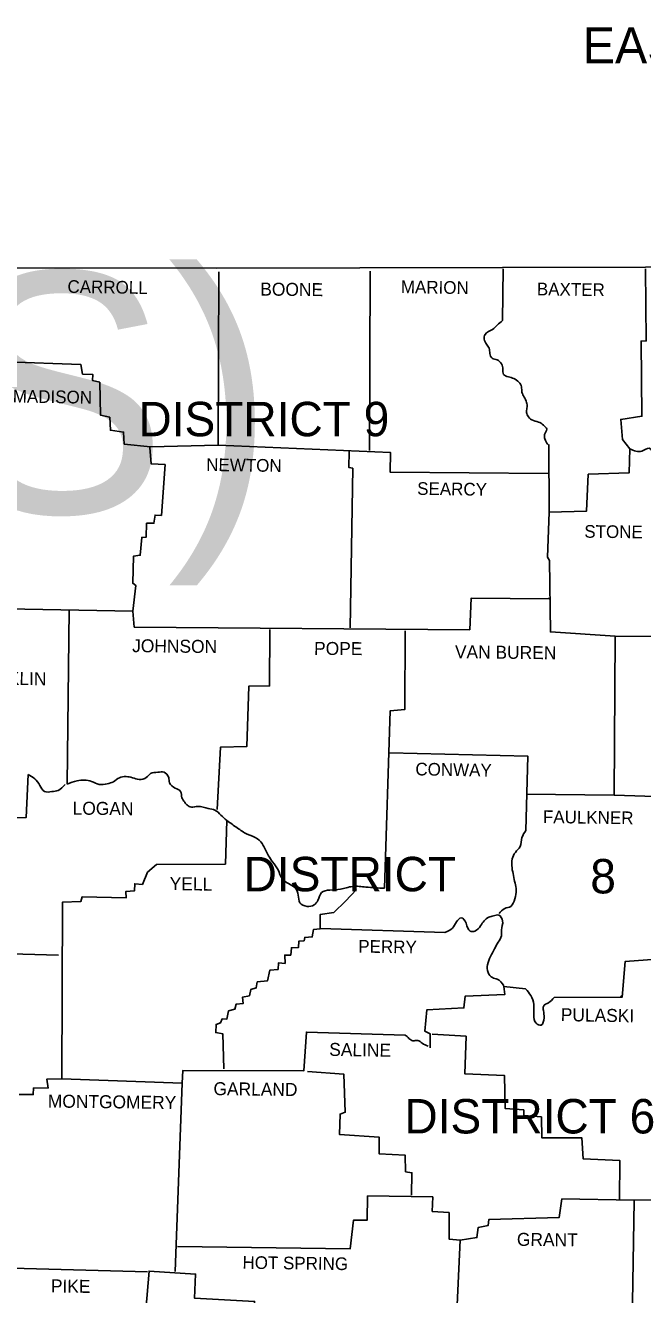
# Model space of a CAD drawing. Extents: x 152 to 3426, y 67 to 2142.
# Drawn here: x 2800 to 2999.8, y 1623.7 to 2035 of the extents above; entities that cross this region are included whole.
import ezdxf

# ---------------------------------------------------------------- set-up
doc = ezdxf.new("R2010")
doc.units = 0
for name, color, linetype in [('R_Border', 7, 'Continuous'), ('R_Grid', 7, 'Continuous'), ('S_AREA_CALC', 7, 'Continuous')]:
    doc.layers.add(name, color=color, linetype=linetype)

msp = doc.modelspace()

# ---------------------------------------------------------------- linework, layer by layer
at = {"layer": 'S_AREA_CALC'}
for points in [[(2703.71, 1956.42), (2861.92, 1956.32), (3000.75, 1956.61), (3164.54, 1959.16), (3240.46, 1960.92)], [(2793.82, 1925.89), (2817.89, 1925.11), (2818.47, 1921.98), (2821.8, 1921.88), (2821.7, 1919.92), (2824.05, 1919.34), (2824.25, 1908.67), (2827.28, 1907.99), (2827.48, 1903.78), (2831.78, 1903.19), (2831.98, 1899.28), (2840.49, 1898.4), (2862.4, 1898.89), (2862.6, 1955.15)], [(2911.62, 1955.34), (2911.33, 1897.22)], [(2954.67, 1956.03), (2954.47, 1939.3)], [(3000.75, 1956.03), (3000.95, 1932.74), (2999.28, 1932.64), (2999.58, 1908.28), (2992.73, 1907.3), (2993.32, 1900.75), (2995.66, 1897.71), (2995.47, 1889.98), (2982.16, 1889.5), (2981.67, 1877.56), (2969.54, 1877.17), (2968.95, 1862.69), (2969.64, 1861.51), (2969.93, 1838.42), (2990.87, 1837.05), (2990.58, 1785.49), (3007.21, 1785), (3007.21, 1732.56), (2994.1, 1731.58), (2993.12, 1720.04), (2971.11, 1719.94)], [(2711.44, 1897.22), (2729.73, 1897.13), (2730.22, 1903.58), (2736.97, 1903.58), (2737.56, 1914.05), (2775.72, 1912.68), (2776.89, 1915.62), (2792.64, 1915.72), (2784.72, 1893.02), (2783.15, 1856.72), (2781.98, 1856.62), (2781.39, 1845.66), (2787.17, 1845.17), (2788.05, 1846.05), (2834.72, 1845.17), (2835.21, 1839.99)], [(2840.29, 1898.2), (2840.68, 1892.92), (2845.18, 1892.63), (2844.01, 1876.19), (2841.96, 1876.29), (2841.56, 1873.65), (2839.22, 1873.65), (2839.12, 1869.14), (2837.65, 1869.05), (2837.16, 1863.27), (2835.01, 1862.98), (2834.72, 1854.17), (2835.69, 1853.49), (2834.72, 1845.17)], [(2862.4, 1898.89), (2918.17, 1896.54), (2918.08, 1890.18), (2969.25, 1889.79)], [(2904.77, 1896.83), (2904.67, 1891.75), (2905.94, 1891.45), (2905.16, 1839.79)], [(2969.54, 1877.17), (2969.44, 1899.18)], [(2835.21, 1839.99), (2943.81, 1839.11), (2944.3, 1849.38), (2969.54, 1849.09)], [(2969.25, 1849.19), (2969.54, 1849.48)], [(2814.17, 1845.56), (2813.48, 1789.11)], [(2879.14, 1839.21), (2879.04, 1820.91), (2872.29, 1820.81), (2871.7, 1801.34), (2863.09, 1801.05), (2862.11, 1780.89)], [(2922.97, 1838.72), (2922.77, 1813.28), (2918.08, 1812.89), (2916.22, 1755.36)], [(2990.87, 1837.05), (3041.16, 1836.76), (3045.46, 1838.81), (3045.17, 1800.56), (3042.24, 1799.29), (3039.59, 1797.04), (3038.71, 1796.16), (3038.62, 1785.2), (3006.62, 1785.2)], [(2917.88, 1799.29), (2962.59, 1798.21), (2962.01, 1774.04)], [(2800.86, 1792.24), (2800.18, 1778.25), (2787.46, 1778.15), (2786.77, 1765.43), (2774.15, 1765.73), (2773.76, 1752.62), (2760.55, 1752.52), (2760.16, 1739.41), (2768.48, 1738.92), (2768.18, 1734.91), (2810.65, 1733.73)], [(2962.1, 1785.88), (2990.58, 1785.49)], [(2865.14, 1777.27), (2864.75, 1763.18), (2842.45, 1763.09), (2839.51, 1760.54), (2837.85, 1756.63), (2835.4, 1756.82), (2835.3, 1754.57), (2832.47, 1754.28), (2832.56, 1752.22), (2818.38, 1752.62), (2817.89, 1751.05), (2812.02, 1750.86), (2811.82, 1693.62), (2806.93, 1693.52), (2807.32, 1690.59), (2802.62, 1690.68), (2802.53, 1688.53), (2797.93, 1688.53)], [(2907.12, 1754.96), (2903.6, 1751.15), (2899.78, 1747.53), (2895.38, 1746.84), (2895.38, 1742.25), (2893.22, 1741.95), (2892.83, 1739.6), (2890.39, 1739.41), (2890.19, 1738.33), (2888.53, 1738.23), (2888.43, 1736.18), (2886.08, 1736.08), (2885.89, 1733.73), (2883.93, 1733.73), (2884.03, 1730.99), (2881.88, 1731.19), (2881.78, 1729.04), (2879.14, 1728.84), (2878.35, 1725.32), (2875.03, 1725.03), (2874.73, 1723.07), (2872.97, 1722.58), (2872.48, 1720.52), (2870.23, 1720.04), (2870.43, 1717.98), (2868.18, 1717.78), (2867.79, 1716.22), (2865.73, 1715.63), (2865.24, 1712.99), (2863.68, 1713.09), (2863.19, 1711.72), (2861.72, 1711.23), (2861.62, 1708.59), (2863.87, 1708.2), (2864.26, 1696.85)], [(2935.79, 1741.07), (2895.47, 1742.34)], [(2961.91, 1722.77), (2954.86, 1723.56), (2955.16, 1720.92), (2942.34, 1720.43), (2941.95, 1716.61), (2929.91, 1715.93), (2929.23, 1709.08), (2930.99, 1708.2), (2930.99, 1703.7)], [(2992.63, 1720.13), (2993.12, 1720.62)], [(2922.97, 1707.81), (2890.97, 1708.78), (2890.09, 1696.16), (2850.96, 1696.36), (2850.76, 1692.15)], [(2931.68, 1708.1), (2942.63, 1707.41), (2942.24, 1695.18), (2955.06, 1694.69), (2955.26, 1684.03), (2961.32, 1683.54), (2961.32, 1681.68), (2967, 1681.29), (2967.19, 1674.44), (2980.11, 1674.44), (2980.5, 1667.69), (2992.44, 1667.1), (2992.34, 1654.38)], [(2891.27, 1695.97), (2903.11, 1695.09), (2903.5, 1682.76), (2901.83, 1682.17), (2901.64, 1675.62), (2914.46, 1674.74), (2914.46, 1669.35), (2922.97, 1668.86), (2923.07, 1663.48), (2925.12, 1663.19), (2925.02, 1655.95)], [(2850.76, 1692.15), (2811.82, 1693.62)], [(2850.76, 1692.15), (2848.51, 1631.2)], [(3109.06, 1665.64), (3072.08, 1666.61), (3071.88, 1654.58), (2997.03, 1654.29)], [(2849.2, 1639.32), (2905.16, 1638.53), (2906.24, 1647.83), (2910.64, 1647.83), (2910.74, 1655.66), (2931.87, 1655.36), (2931.68, 1650.67), (2937.16, 1650.27), (2937.16, 1641.66), (2940.68, 1641.37)], [(2940.68, 1641.37), (2946.16, 1642.15), (2946.55, 1645.48), (2949.78, 1646.07), (2949.97, 1648.02), (2972.77, 1648.71), (2973.65, 1654.68), (2997.03, 1654.29)], [(2997.03, 1654.09), (2996.45, 1614.56), (2994.2, 1614.47), (2993.9, 1589.91)], [(2940.68, 1641.37), (2939.5, 1615.74), (2938.62, 1616.03), (2938.72, 1602.72)], [(2783.55, 1632.57), (2839.51, 1631.1)], [(2837.65, 1613.19), (2837.46, 1618.57), (2839.02, 1618.67), (2840, 1631.29), (2855.07, 1630.32), (2854.68, 1622.59), (2874.15, 1621.51), (2874.24, 1616.81), (2891.85, 1615.74), (2894.89, 1610.45), (2893.03, 1608.11), (2893.91, 1604.49), (2957.7, 1602.14)]]:
    msp.add_lwpolyline(points, dxfattribs=at)
for points in [[(2954.47, 1939.3), (2952.71, 1937.83), (2951.15, 1936.46), (2948.8, 1934.8), (2948.5, 1933.23), (2949.29, 1931.66), (2950.07, 1930.39), (2950.36, 1928.63), (2951.05, 1927.16), (2952.71, 1926.58), (2954.08, 1925.31), (2954.57, 1923.54), (2954.77, 1921.88), (2956.33, 1921.1), (2958.09, 1920.51), (2959.76, 1919.34), (2960.54, 1917.87), (2960.73, 1916.01), (2961.42, 1914.54), (2962.2, 1912.78), (2962.4, 1911.31), (2962.2, 1909.85), (2962.59, 1908.48), (2963.87, 1907.11), (2966.12, 1906.42), (2967.68, 1905.44), (2968.76, 1904.07), (2968.07, 1902.41), (2968.17, 1900.94), (2969.05, 1899.18)], [(2995.66, 1897.71), (2999.58, 1897.03), (3001.93, 1897.91), (3003.59, 1895.37), (3004.47, 1893.41), (3005.94, 1890.57), (3008.29, 1889.69), (3010.05, 1888.13), (3010.05, 1886.46), (3008.48, 1884.9), (3007.31, 1883.33), (3007.7, 1881.47), (3008.09, 1878.93), (3008.09, 1876.48), (3007.5, 1874.23), (3007.01, 1872.18), (3007.5, 1870.42), (3009.36, 1870.71), (3011.32, 1872.18), (3013.37, 1872.18), (3015.33, 1871.1), (3017.38, 1869.24), (3019.44, 1869.63), (3021.1, 1870.12), (3023.45, 1870.81), (3025.11, 1869.93), (3026.58, 1868.75), (3028.34, 1866.89), (3030.01, 1865.72), (3032.16, 1864.64), (3034.8, 1863.96), (3037.25, 1862.3), (3037.64, 1859.46), (3037.54, 1857.01), (3037.34, 1853.98), (3037.15, 1850.65), (3037.44, 1847.42), (3038.52, 1845.27), (3039.89, 1842.73), (3040.28, 1840.38), (3040.18, 1836.66)], [(2813.48, 1789.11), (2816.71, 1790.19), (2819.06, 1790.38), (2821.41, 1789.99), (2823.86, 1789.01), (2826.5, 1789.21), (2828.45, 1789.89), (2830.41, 1791.17), (2832.56, 1791.56), (2834.62, 1791.17), (2836.77, 1790.58), (2839.12, 1791.26), (2840.49, 1792.54), (2842.84, 1792.93), (2844.89, 1792.93), (2846.36, 1791.26), (2846.65, 1789.5), (2848.51, 1787.84), (2850.17, 1786.76), (2850.66, 1784.71), (2851.54, 1783.24), (2852.43, 1782.26), (2853.7, 1781.67), (2855.85, 1781.87), (2859.18, 1781.19), (2861.33, 1780.7), (2863.29, 1779.03), (2865.14, 1777.27)], [(2800.86, 1792.24), (2803.02, 1790.87), (2804.68, 1788.62), (2806.15, 1786.76), (2808.59, 1786.66), (2810.55, 1787.06), (2812.8, 1789.01)], [(2865.14, 1777.27), (2868.57, 1774.92), (2871.8, 1772.87), (2875.12, 1771.4), (2876.98, 1769.25), (2878.65, 1765.92), (2880.02, 1763.87), (2881.78, 1761.32), (2883.05, 1758.49), (2885.1, 1756.92), (2887.26, 1755.55), (2888.33, 1753.11), (2888.82, 1750.66), (2891.17, 1749.49), (2893.42, 1749.97), (2894.69, 1751.44), (2895.87, 1753.99), (2898.51, 1754.77), (2901.93, 1755.06), (2905.85, 1755.94), (2910.15, 1755.75), (2916.22, 1755.36)], [(2962.01, 1774.04), (2960.73, 1771.79), (2960.15, 1768.86), (2958.58, 1767), (2957.6, 1764.85), (2957.51, 1762.01), (2958, 1759.47), (2958.48, 1757.02), (2958.88, 1754.77), (2958.39, 1751.93), (2957.11, 1749.49), (2955.16, 1748.8), (2953.3, 1747.14)], [(2935.79, 1741.07), (2938.23, 1742.44), (2939.5, 1744.5), (2941.07, 1745.77), (2942.63, 1744.01), (2944, 1741.46), (2945.47, 1741.46), (2947.33, 1743.22), (2948.5, 1744.79), (2949.97, 1745.96), (2951.54, 1746.45), (2953.2, 1746.65), (2954.47, 1744.79), (2954.08, 1741.85), (2954.08, 1739.9), (2953.01, 1737.84), (2951.83, 1735.69), (2950.56, 1733.24), (2949.58, 1730.6), (2949.78, 1728.06), (2951.15, 1726.39), (2952.71, 1725.91), (2954.86, 1723.75)], [(2961.91, 1722.77), (2963.57, 1720.62), (2964.55, 1717.69), (2964.55, 1714.36), (2965.33, 1711.62), (2966.9, 1711.03), (2967.88, 1713.38), (2967.68, 1715.73), (2967.68, 1717.1), (2969.34, 1718.27), (2971.11, 1719.94)], [(2930.31, 1704.19), (2928.45, 1705.16), (2926.98, 1706.04), (2925.41, 1705.95), (2924.14, 1706.73), (2922.97, 1707.81)]]:
    msp.add_spline(points, degree=3, dxfattribs=at)

# ---------------------------------------------------------------- texts
at = {"layer": 'R_Border'}
for height, p in [(11.724, (2980.36, 2022.61)), (78, (1170.86, 1876.96))]:
    msp.add_text('EASSIS CREEK STR. & APPRS. (S)', height=height, dxfattribs=at).set_placement(p)
for s, height, rotation, p in [('CARROLL', 4.109, 359.1481, (2813.58, 1948.3)), ('BOONE', 4.207, 359.4001, (2876, 1947.42)), ('MARION', 4.109, 359.1854, (2921.5, 1948.2)), ('BAXTER', 4.109, 359.2559, (2965.53, 1947.51)), ('MADISON', 4.109, 359.0906, (2795.87, 1912.78)), ('NEWTON', 4.109, 359.2717, (2858.49, 1890.57)), ('SEARCY', 4.108, 359.2527, (2926.78, 1882.84)), ('STONE', 4.108, 359.4001, (2980.89, 1868.95)), ('JOHNSON', 4.207, 359.3514, (2834.52, 1831.87)), ('POPE', 4.207, 359.6155, (2893.42, 1830.99)), ('VAN BUREN', 4.207, 359.3508, (2939.01, 1829.91)), ('FRANKLIN', 4.207, 359.1815, (2778.95, 1821.5)), ('CONWAY', 4.108, 359.0371, (2926.2, 1791.95)), ('LOGAN', 4.207, 359.3969, (2815.25, 1779.23)), ('FAULKNER', 4.109, 359.2486, (2967.49, 1776.49)), ('YELL', 4.207, 359.1987, (2846.65, 1754.77)), ('PERRY', 4.109, 359.0858, (2907.71, 1734.52)), ('PULASKI', 4.207, 359.053, (2973.26, 1712.31)), ('SALINE', 4.207, 359.1491, (2898.31, 1701.05)), ('GARLAND', 4.207, 359.3658, (2860.84, 1688.33)), ('MONTGOMERY', 4.207, 359.2944, (2807.22, 1684.32)), ('GRANT', 4.207, 359.4032, (2959.07, 1639.51)), ('HOT SPRING', 4.109, 359.2216, (2870.23, 1632.08)), ('PIKE', 4.206, 359.0452, (2808.2, 1624.44))]:
    msp.add_text(s, height=height, rotation=rotation, dxfattribs=at).set_placement(p)
at = {"layer": 'R_Grid'}
for s, height, p in [('DISTRICT 9', 11.154, (2836.57, 1901.82)), ('DISTRICT', 11.154, (2870.62, 1754.38)), ('8', 11.15, (2982.85, 1753.69)), ('DISTRICT 6', 11.154, (2922.67, 1675.91))]:
    msp.add_text(s, height=height, dxfattribs=at).set_placement(p)

doc.saveas('drawing.dxf')
